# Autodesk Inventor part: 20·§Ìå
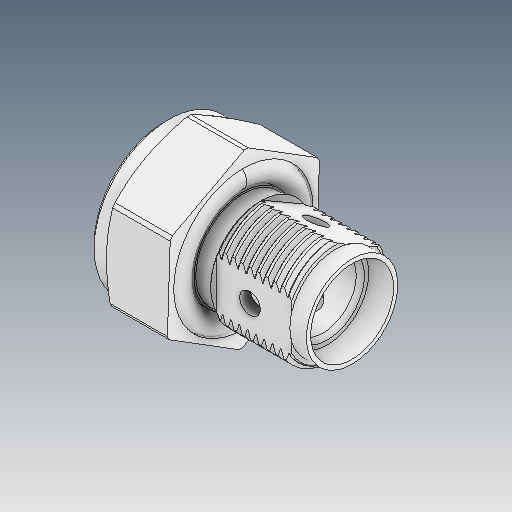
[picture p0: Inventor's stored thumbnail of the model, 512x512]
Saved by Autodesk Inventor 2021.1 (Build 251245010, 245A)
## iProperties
Created: 2021-05
Part Number: 20·§Ìå
Material: Ogólny
Document SubType Name: Modeling
Designer: user
Density: 1 g/cm^3
Appearance: Domyślna
Author: user
Revision Number: ÈÎºÎ
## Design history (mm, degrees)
feature "ÊäÈë1"
feature "ÊäÈë2"
node "Bryła1"
node "Bryła2"
